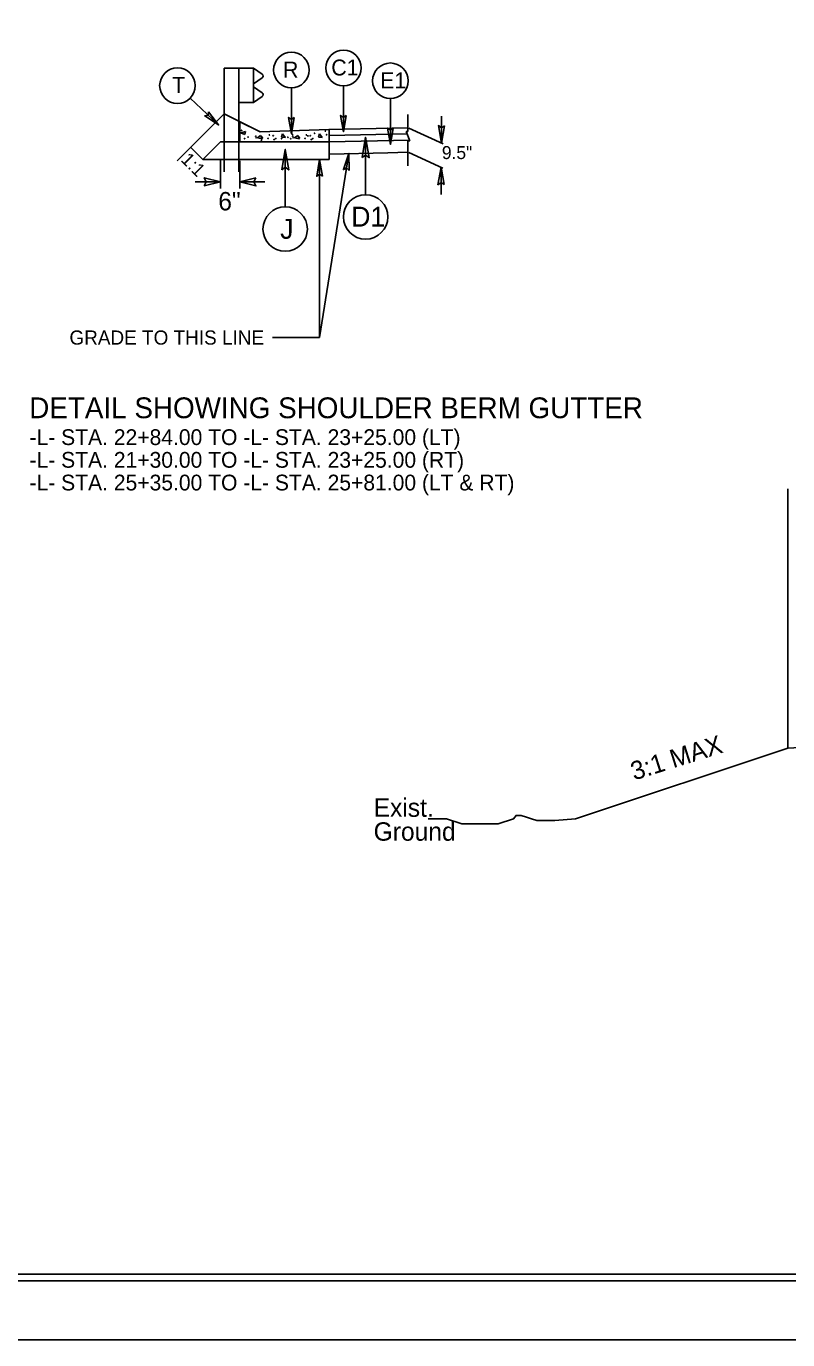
# Model space of a CAD drawing. Extents: x 1497225 to 1499181, y 579958 to 582278.
# Drawn here: x 1497879 to 1498169, y 581178 to 581678 of the extents above; entities that cross this region are included whole.
import ezdxf

# ---------------------------------------------------------------- set-up
doc = ezdxf.new("R2010")
doc.units = 0
for name, color, linetype in [('Old_Level_1', 7, 'Continuous'), ('Old_Level_13', 7, 'Continuous'), ('Old_Level_4', 7, 'Continuous'), ('Prop Dimension', 7, 'Continuous'), ('Prop Terminator CELL', 7, 'Continuous'), ('Sheet Cutting Line CELL', 7, 'Continuous'), ('Sheet Plot Border Inside CELL', 7, 'Continuous'), ('Sheet Plot Border Outside CELL', 7, 'Continuous'), ('Sheet Typical CELL', 7, 'Continuous'), ('Typical Curb CELL', 7, 'Continuous'), ('Typical Guardrail CELL', 7, 'Continuous'), ('Typical ID Circle CELL', 7, 'Continuous'), ('Typical Pavement Slope CELL', 7, 'Continuous'), ('Typical Pavement Slope Information CELL', 7, 'Continuous'), ('Typical Shoulder Slope CELL', 7, 'Continuous'), ('Typical Terminator CELL', 7, 'Continuous'), ('Typical Text General CELL', 7, 'Continuous'), ('Typical Text ID Circle CELL', 7, 'Continuous')]:
    doc.layers.add(name, color=color, linetype=linetype)

# ---------------------------------------------------------------- blocks, each defined once
blk = doc.blocks.new('TERMINATOR')
at = {"layer": 'Typical Terminator CELL'}
blk.add_lwpolyline([(-0.469, 0.081), (0, 0), (-0.471, -0.083), (-0.411, 0)], close=True, dxfattribs=at)

msp = doc.modelspace()

# ---------------------------------------------------------------- linework, layer by layer
at = {"layer": 'Old_Level_1'}
for p, q in [((1497952.56, 581616.27), (1497952.56, 581626.94)), ((1497959.91, 581616.27), (1497959.91, 581626.85)), ((1497952.56, 581618.84), (1497942.94, 581618.84)), ((1497959.91, 581618.84), (1497969.53, 581618.84)), ((1498168.53, 581403.22), (1498168.53, 581501.93)), ((1498087.75, 581376.29), (1498168.53, 581403.22)), ((1498168.53, 581403.22), (1498216.42, 581405.87))]:
    msp.add_line(p, q, dxfattribs=at)
msp.add_lwpolyline([(1498087.75, 581376.29), (1498079.88, 581375.63), (1498077.91, 581375.63), (1498074.96, 581375.63), (1498072.99, 581375.63), (1498071.02, 581376.29), (1498069.06, 581376.95), (1498067.09, 581377.6), (1498065.12, 581377.6), (1498064.14, 581376.29), (1498062.17, 581375.63), (1498060.2, 581374.98), (1498058.24, 581374.32), (1498056.27, 581374.32), (1498054.3, 581374.32), (1498052.34, 581374.32), (1498050.37, 581374.32), (1498048.4, 581374.32), (1498046.44, 581374.32), (1498044.47, 581374.32), (1498042.5, 581374.98), (1498040.54, 581375.63), (1498038.57, 581376.29), (1498035.61, 581376.29), (1498033.65, 581376.29), (1498031.68, 581376.29)], dxfattribs=at)
at = {"layer": 'Old_Level_4'}
msp.add_line((1497945.88, 581627.32), (1497941.25, 581631.95), dxfattribs=at)
at = {"layer": 'Prop Dimension'}
for p, q in [((1498036.69, 581643.82), (1498036.69, 581633.57)), ((1498024.31, 581639.21), (1498037.32, 581633.28)), ((1498024.31, 581629.93), (1498037.17, 581624.07)), ((1498036.54, 581614), (1498036.54, 581624.36)), ((1497990.34, 581559.57), (1497972.36, 581559.57))]:
    msp.add_line(p, q, dxfattribs=at)
at = {"layer": 'Prop Terminator CELL'}
for points in [[(1497991.43, 581620.97), (1497990.34, 581627.32), (1497989.21, 581620.93), (1497990.34, 581621.74)], [(1498001.58, 581623.19), (1498001.5, 581629.63), (1497999.38, 581623.5), (1498000.62, 581624.13)]]:
    msp.add_lwpolyline(points, close=True, dxfattribs=at)
at = {"layer": 'Sheet Cutting Line CELL'}
msp.add_line((1497225.23, 581177.96), (1498909.23, 581177.96), dxfattribs=at)
at = {"layer": 'Sheet Plot Border Inside CELL'}
msp.add_lwpolyline([(1498904.73, 582255.51), (1497238.23, 582255.51), (1497238.23, 581200.41), (1498904.73, 581200.41)], close=True, dxfattribs=at)
at = {"layer": 'Sheet Plot Border Outside CELL'}
msp.add_lwpolyline([(1498909.23, 582277.96), (1497225.23, 582277.96), (1497225.23, 581177.96), (1498909.23, 581177.96)], close=True, dxfattribs=at)
at = {"layer": 'Sheet Typical CELL'}
msp.add_lwpolyline([(1498892.23, 582252.96), (1497392.23, 582252.96), (1497392.23, 581202.96), (1498892.23, 581202.96)], close=True, dxfattribs=at)
at = {"layer": 'Typical Curb CELL'}
for p, q in [((1497959.91, 581634.05), (1497959.91, 581641.69)), ((1497967.66, 581637.81), (1497959.91, 581641.69)), ((1497960.32, 581637.42), (1497962.06, 581637.93)), ((1497961.87, 581636.9), (1497960.32, 581637.42)), ((1497962.06, 581637.93), (1497961.87, 581636.9)), ((1497993.87, 581638.75), (1497967.66, 581637.81)), ((1497994, 581638.75), (1497994, 581638.75)), ((1497994, 581634.05), (1497994, 581638.63)), ((1497959.91, 581634.05), (1497994, 581634.05)), ((1497967.88, 581636.48), (1497966.71, 581635.63)), ((1497966.71, 581635.63), (1497968.58, 581635.19)), ((1497968.58, 581635.19), (1497967.88, 581636.48)), ((1497976.25, 581637.11), (1497975.86, 581635.83)), ((1497975.86, 581635.83), (1497977.21, 581635.76)), ((1497977.21, 581635.76), (1497976.25, 581637.11)), ((1497981.97, 581636.48), (1497980.81, 581635.63)), ((1497980.81, 581635.63), (1497982.68, 581635.19)), ((1497982.68, 581635.19), (1497981.97, 581636.48)), ((1497990.34, 581637.11), (1497989.95, 581635.83)), ((1497989.95, 581635.83), (1497991.32, 581635.76)), ((1497991.32, 581635.76), (1497990.34, 581637.11))]:
    msp.add_line(p, q, dxfattribs=at)
for centre in [(1497960.64, 581638.38), (1497988.41, 581637.31), (1497992.55, 581638.16), (1497961.73, 581635.3), (1497963.09, 581635.87), (1497965.99, 581636.19), (1497966.18, 581635.63), (1497968.18, 581634.66), (1497968.5, 581635.81), (1497970.69, 581635.37), (1497971.22, 581636.67), (1497972.64, 581636.35), (1497973.01, 581634.92), (1497973.64, 581635.3), (1497975.83, 581635.3), (1497977.18, 581635.87), (1497978.24, 581635.77), (1497979.33, 581635.25), (1497979.97, 581636.86), (1497980.08, 581636.19), (1497980.28, 581635.63), (1497982.6, 581635.81), (1497984.79, 581635.37), (1497985.32, 581636.67), (1497985.88, 581636.32), (1497986.73, 581636.35), (1497987.11, 581634.92), (1497987.74, 581635.3), (1497992.98, 581636.74)]:
    msp.add_circle(centre, 0.0905, dxfattribs=at)
msp.add_arc((1497993.88, 581638.63), 0.118, 0, 92.048, dxfattribs=at)
at = {"layer": 'Typical Guardrail CELL'}
for p, q in [((1497959.58, 581662.12), (1497953.96, 581662.12)), ((1497953.96, 581662.12), (1497953.96, 581634.06)), ((1497959.58, 581662.12), (1497959.58, 581634.06)), ((1497959.58, 581662.12), (1497965.19, 581662.12)), ((1497965.19, 581662.12), (1497965.19, 581649.03)), ((1497965.19, 581662.12), (1497968.46, 581659.83)), ((1497965.19, 581656.1), (1497968.46, 581658.39)), ((1497965.19, 581655.57), (1497965.19, 581656.1)), ((1497965.19, 581655.57), (1497965.19, 581655.04)), ((1497965.19, 581655.04), (1497968.46, 581652.75)), ((1497959.58, 581649.03), (1497965.19, 581649.03)), ((1497965.19, 581649.03), (1497968.46, 581651.32)), ((1497959.58, 581634.06), (1497953.96, 581634.06)), ((1497953.96, 581634.06), (1497953.96, 581622.68)), ((1497959.58, 581634.06), (1497959.58, 581622.68))]:
    msp.add_line(p, q, dxfattribs=at)
for centre, start, end in [((1497967.96, 581659.11), 304.9888, 54.997), ((1497967.96, 581652.03), 304.9634, 54.9941)]:
    msp.add_arc(centre, 0.876, start, end, dxfattribs=at)
at = {"layer": 'Typical ID Circle CELL'}
for p, q in [((1497979.58, 581654.63), (1497979.58, 581637.13)), ((1497999.4, 581655.41), (1497999.4, 581637.92)), ((1497940.99, 581650.66), (1497951.86, 581640.47)), ((1498017.27, 581650.54), (1498017.27, 581633.04)), ((1498007.82, 581613.93), (1498007.82, 581635.8)), ((1497977.22, 581609.29), (1497977.22, 581631.16)), ((1497990.34, 581559.57), (1498001.46, 581629.56)), ((1497990.34, 581559.57), (1497990.34, 581627.32))]:
    msp.add_line(p, q, dxfattribs=at)
for centre, radius in [((1497979.58, 581661.39), 6.77), ((1497999.4, 581662.18), 6.77), ((1498017.27, 581657.3), 6.77), ((1497936.2, 581655.45), 6.77), ((1498007.82, 581605.47), 8.46), ((1497977.22, 581600.83), 8.46)]:
    msp.add_circle(centre, radius, dxfattribs=at)
at = {"layer": 'Typical Pavement Slope CELL'}
for p, q in [((1497967.66, 581637.81), (1497953.96, 581644.66)), ((1497952.61, 581634.05), (1497945.88, 581627.32)), ((1497959.91, 581634.05), (1497952.61, 581634.05)), ((1497994, 581627.32), (1497945.88, 581627.32)), ((1497994.05, 581629.41), (1498016.29, 581629.86)), ((1498016.29, 581629.86), (1498023.97, 581630.09))]:
    msp.add_line(p, q, dxfattribs=at)
at = {"layer": 'Typical Pavement Slope Information CELL'}
for p, q in [((1498023.97, 581644.49), (1498023.97, 581637.99)), ((1498023.21, 581637.99), (1498023.97, 581637.99)), ((1498023.21, 581637.99), (1498024.72, 581634.38)), ((1498023.97, 581634.38), (1498023.97, 581624.91)), ((1498023.97, 581634.38), (1498024.72, 581634.38))]:
    msp.add_line(p, q, dxfattribs=at)
at = {"layer": 'Typical Shoulder Slope CELL'}
for p, q in [((1497953.96, 581644.66), (1497936.12, 581626.82)), ((1497993.87, 581638.75), (1498023.97, 581639.36)), ((1497994, 581636.49), (1498023.59, 581637.1)), ((1497994, 581634.05), (1498024.6, 581634.67)), ((1497994, 581634.05), (1497994, 581627.32))]:
    msp.add_line(p, q, dxfattribs=at)
at = {"layer": 'Typical Terminator CELL'}
for points in [[(1497948.08, 581645.48), (1497951.86, 581640.47), (1497946.57, 581643.92), (1497947.9, 581644.18)], [(1497980.64, 581643.32), (1497979.58, 581637.13), (1497978.48, 581643.35), (1497979.58, 581642.56)], [(1498000.46, 581644.1), (1497999.4, 581637.92), (1497998.3, 581644.14), (1497999.4, 581643.35)], [(1498018.34, 581639.23), (1498017.27, 581633.04), (1498016.17, 581639.26), (1498017.27, 581638.47)], [(1498037.83, 581640.18), (1498036.69, 581633.57), (1498035.52, 581640.21), (1498036.69, 581639.37)], [(1498006.49, 581628.07), (1498007.82, 581635.8), (1498009.19, 581628.03), (1498007.82, 581629.02)], [(1497975.88, 581623.43), (1497977.22, 581631.16), (1497978.59, 581623.38), (1497977.22, 581624.37)], [(1498037.68, 581617.75), (1498036.54, 581624.36), (1498035.36, 581617.71), (1498036.54, 581618.55)]]:
    msp.add_lwpolyline(points, close=True, dxfattribs=at)

# ---------------------------------------------------------------- block references
at = {"layer": 'Old_Level_4', "xscale": 13.123011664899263, "yscale": -18.835616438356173}
for p, rotation in [((1497952.56, 581618.84), 3.946795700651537e-12), ((1497959.91, 581618.84), -179.99999999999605)]:
    msp.add_blockref('TERMINATOR', p, dxfattribs=dict(at, rotation=rotation))

# ---------------------------------------------------------------- texts
at = {"layer": 'Old_Level_1'}
for s, rotation, p in [('3:1 MAX', 17.4404, (1498110.05, 581390.85)), ('Exist.', 359.9492, (1498010.89, 581377.07)), ('Ground', 359.9492, (1498010.88, 581367.97))]:
    msp.add_text(s, height=7, rotation=rotation, dxfattribs=at).set_placement(p)
at = {"layer": 'Old_Level_13'}
for s, p in [('-L- STA. 22+84.00 TO -L- STA. 23+25.00 (LT)', (1497879.88, 581518.61)), ('-L- STA. 21+30.00 TO -L- STA. 23+25.00 (RT)', (1497879.88, 581509.97)), ('-L- STA. 25+35.00 TO -L- STA. 25+81.00 (LT & RT)', (1497879.88, 581501.32))]:
    msp.add_text(s, height=6, dxfattribs=at).set_placement(p)
at = {"layer": 'Old_Level_4'}
for s, height, rotation, p in [('9.5"', 4.95, 360, (1498036.87, 581627.48)), ('1:1', 4.95, 315, (1497937.25, 581626.92)), ('6"', 7, 360, (1497951.74, 581607.95)), ('DETAIL SHOWING SHOULDER BERM GUTTER', 7.92, 360, (1497879.78, 581528.82))]:
    msp.add_text(s, height=height, rotation=rotation, dxfattribs=at).set_placement(p)
at = {"layer": 'Typical Text General CELL'}
msp.add_text('GRADE TO THIS LINE', height=5.3887, dxfattribs=at).set_placement((1497895.09, 581556.84))
at = {"layer": 'Typical Text ID Circle CELL'}
for s, height, p in [('R', 6.06, (1497976.4, 581658.53)), ('C1', 6.06, (1497994.77, 581659.32)), ('T', 6.06, (1497934.18, 581652.66)), ('E1', 6.06, (1498013.38, 581654.44)), ('D1', 7.575, (1498002.36, 581601.78)), ('J', 7.58, (1497975.31, 581597.13))]:
    msp.add_text(s, height=height, dxfattribs=at).set_placement(p)

doc.saveas('drawing.dxf')
